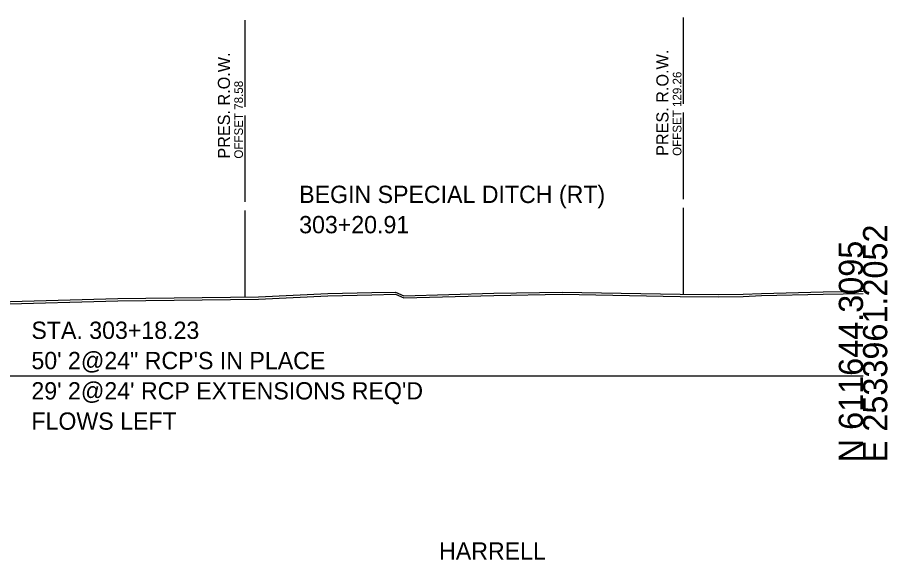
# Model space of a CAD drawing. Extents: x -192 to 2669, y -25 to 8040.
# Drawn here: x 202.3 to 302.8, y 3978.7 to 4041.4 of the extents above; entities that cross this region are included whole.
import ezdxf

# ---------------------------------------------------------------- set-up
doc = ezdxf.new("R2010")
doc.units = 0
for name, color, linetype in [('DESIGN - SHEET - Light Grid', 7, 'Continuous'), ('DESIGN - TRANSPORTATION - Text', 7, 'Continuous'), ('DESIGN - TYPICAL - Warning Text', 7, 'Continuous'), ('SURVEY - GROUND - Bottom of Topsoil Layer', 7, 'Continuous'), ('SURVEY - GROUND - Top of Ground', 7, 'Continuous'), ('SURVEY - PROPERTY - ROW Lines', 7, 'Continuous'), ('SURVEY - PROPERTY - ROW Lines Text', 7, 'Continuous')]:
    doc.layers.add(name, color=color, linetype=linetype)

msp = doc.modelspace()

# ---------------------------------------------------------------- linework, layer by layer
at = {"layer": 'DESIGN - SHEET - Light Grid'}
msp.add_line((150, 4000), (300, 4000), dxfattribs=at)
at = {"layer": 'SURVEY - GROUND - Bottom of Topsoil Layer'}
for p, q in [((230.11, 4008.87), (238.15, 4009.25)), ((238.15, 4009.25), (243.24, 4009.37)), ((243.24, 4009.37), (245.95, 4009.43)), ((245.95, 4009.43), (246.93, 4008.99)), ((246.93, 4008.99), (257.31, 4009.29)), ((257.31, 4009.29), (265.24, 4009.42)), ((265.24, 4009.42), (278.87, 4009.18)), ((278.87, 4009.18), (283.31, 4009.13)), ((283.31, 4009.13), (286.15, 4009.18)), ((286.15, 4009.18), (288.25, 4009.26)), ((288.25, 4009.26), (295.4, 4009.44)), ((295.4, 4009.44), (300, 4009.51)), ((190.36, 4008.03), (213.87, 4008.68)), ((213.87, 4008.68), (230.11, 4008.87))]:
    msp.add_line(p, q, dxfattribs=at)
at = {"layer": 'SURVEY - GROUND - Top of Ground'}
msp.add_lwpolyline([(190.36, 4008.28), (213.87, 4008.93), (230.11, 4009.12), (238.15, 4009.5), (243.24, 4009.62), (245.95, 4009.68), (246.93, 4009.24), (257.31, 4009.54), (265.24, 4009.67), (278.87, 4009.43), (283.31, 4009.38), (286.15, 4009.43), (288.25, 4009.51), (295.4, 4009.69), (300, 4009.76)], dxfattribs=at)
at = {"layer": 'SURVEY - PROPERTY - ROW Lines'}
for p, q in [((279.26, 4031.42), (279.26, 4041.42)), ((228.58, 4031.1), (228.58, 4041.1)), ((279.26, 4020.42), (279.26, 4030.42)), ((228.58, 4020.1), (228.58, 4030.1)), ((279.26, 4009.42), (279.26, 4019.42)), ((228.58, 4009.1), (228.58, 4019.1))]:
    msp.add_line(p, q, dxfattribs=at)

# ---------------------------------------------------------------- texts
at = {"layer": 'DESIGN - SHEET - Light Grid'}
for s, p in [('E 2533961.2052', (302.8, 3990)), ('N 611644.3095', (300, 3990))]:
    msp.add_text(s, height=2.8, rotation=90, dxfattribs=at).set_placement(p)
at = {"layer": 'DESIGN - TRANSPORTATION - Text'}
for s, p in [('BEGIN SPECIAL DITCH (RT)', (234.83, 4019.97)), ('303+20.91', (234.83, 4016.47)), ('STA. 303+18.23', (203.88, 4004.26)), ('50\' 2@24" RCP\'S IN PLACE', (203.88, 4000.76)), ("29' 2@24' RCP EXTENSIONS REQ'D", (203.88, 3997.26)), ('FLOWS LEFT', (203.88, 3993.76))]:
    msp.add_text(s, height=2, dxfattribs=at).set_placement(p)
at = {"layer": 'DESIGN - TYPICAL - Warning Text'}
msp.add_text('HARRELL', height=2, dxfattribs=at).set_placement((251, 3978.75))
at = {"layer": 'SURVEY - PROPERTY - ROW Lines Text'}
for s, height, p in [('PRES. R.O.W.', 1.4, (277.51, 4025.42)), ('PRES. R.O.W.', 1.4, (226.83, 4025.1)), ('OFFSET 129.26', 1, (279.01, 4025.42)), ('OFFSET 78.58', 1, (228.33, 4025.1))]:
    msp.add_text(s, height=height, rotation=90, dxfattribs=at).set_placement(p)

doc.saveas('drawing.dxf')
